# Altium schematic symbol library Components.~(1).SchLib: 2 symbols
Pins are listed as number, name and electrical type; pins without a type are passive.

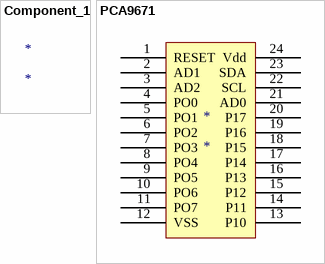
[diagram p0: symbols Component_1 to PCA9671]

## Component_1
designator *

## PCA9671
designator *
pins: 1 RESET, 2 AD1, 3 AD2, 4 PO0, 5 PO1, 6 PO2, 7 PO3, 8 PO4, 9 PO5, 10 PO6, 11 PO7, 12 VSS, 13 P10, 14 P11, 15 P12, 16 P13, 17 P14, 18 P15, 19 P16, 20 P17, 21 AD0, 22 SCL, 23 SDA, 24 Vdd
